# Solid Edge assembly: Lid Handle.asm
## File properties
Author: m_hel
Template: iso metric assembly.asm
Last saved by: m_hel
Revision: 3
Application: Solid Edge
Username: m_hel
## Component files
Lid Handle Base.psm
Lid Handle.par
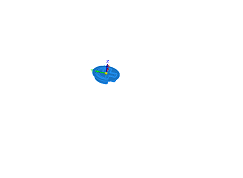
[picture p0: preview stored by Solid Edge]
